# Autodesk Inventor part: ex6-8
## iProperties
Shininess: 64.0
Length Units: 11272
Angle Units: 11279
Time Units: 11290
Mass Units: 11286
Length Display Precision: 3
Angle Display Precision: 2
Compacted: True
Part Number: ex6-8
Document SubType Name: Modeling
Created: 2002-09
Designer: Elise Moss
Density: 0.0
Volumn: 0.0
Area: 0.0
PropertySet Name: Model Information
Control State: 0
Master: False
Checked Out: False
Author: Elise Moss
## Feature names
1. Revolution1
2. Shell1
3. Hole1
4. Loft1
5. Sweep1
6. Coil1
